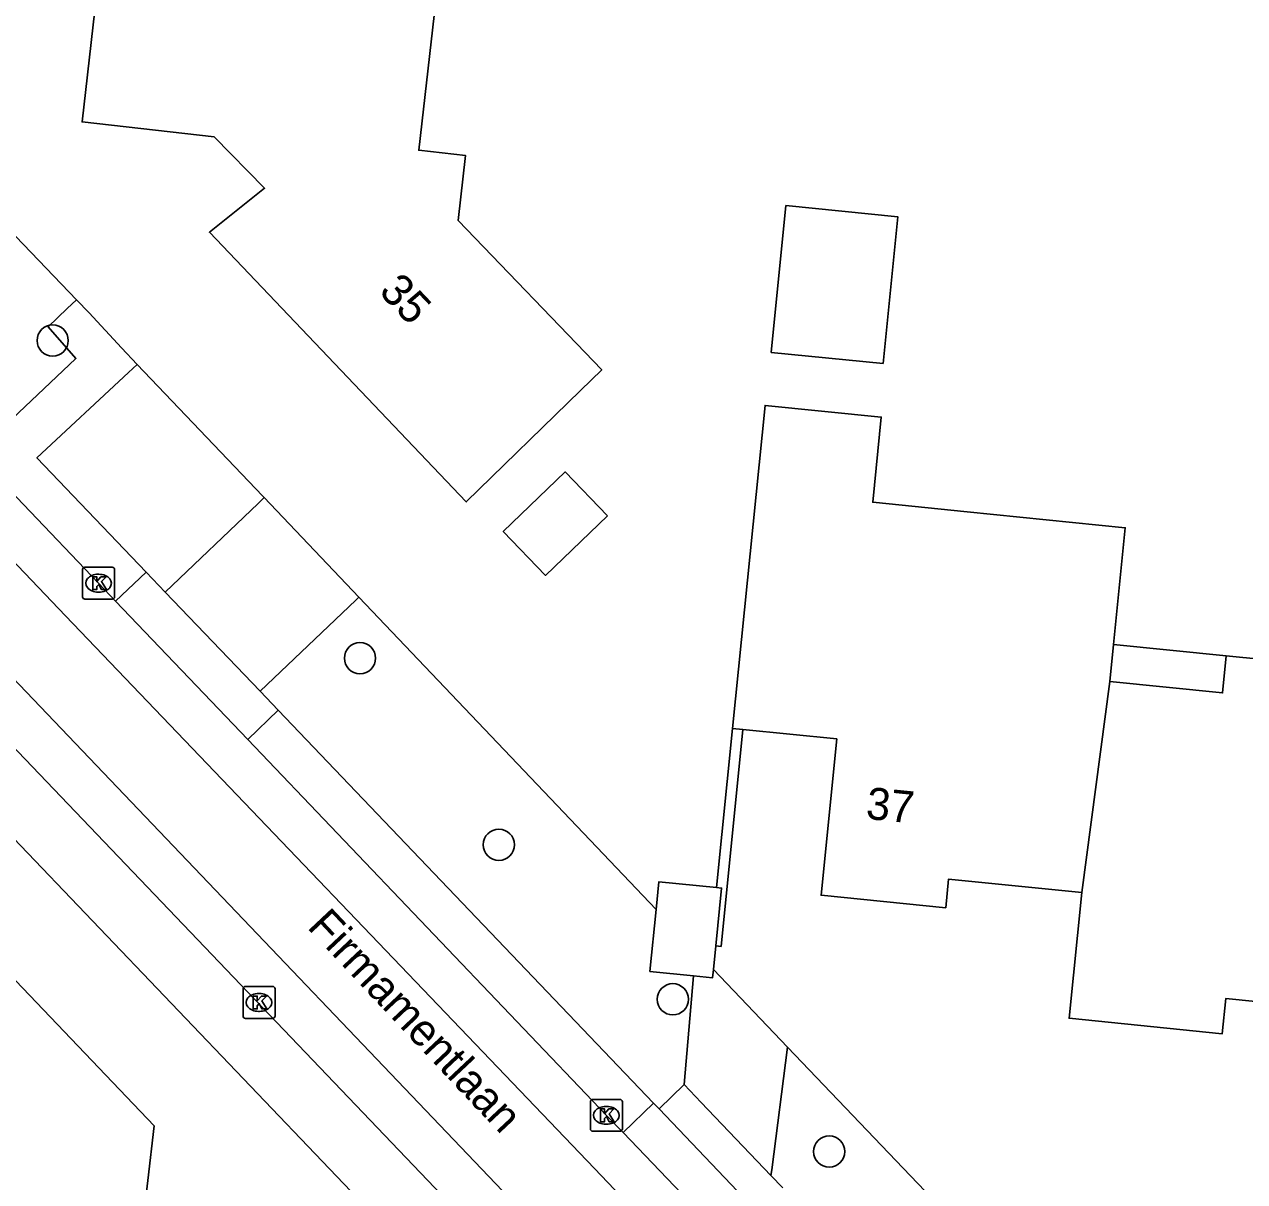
# Model space of a CAD drawing. Extents: x 162398 to 163643, y 386453 to 387397.
# Drawn here: x 162909.4 to 162947.59, y 386547.61 to 386583.81 of the extents above; entities that cross this region are included whole.
import ezdxf

# ---------------------------------------------------------------- set-up
doc = ezdxf.new("R2010")
doc.units = 0
for name, color, linetype in [('IMGEO_Boom', 7, 'Continuous'), ('IMGEO_Groenvoorziening', 7, 'Continuous'), ('IMGEO_Kolk', 7, 'Continuous'), ('IMGEO_Muur', 7, 'Continuous'), ('IMGEO_Openbare_ruimte_label', 7, 'Continuous'), ('IMGEO_Pand', 7, 'Continuous'), ('IMGEO_Pand_nummerreeks', 7, 'Continuous'), ('IMGEO_Pand_overbouw', 7, 'Continuous'), ('IMGEO_Rijbaan_lokaal_gesloten', 7, 'Continuous'), ('IMGEO_Rijbaan_lokaal_open', 7, 'Continuous'), ('IMGEO_Voetpad_open', 7, 'Continuous')]:
    doc.layers.add(name, color=color, linetype=linetype)

msp = doc.modelspace()

# ---------------------------------------------------------------- linework, layer by layer
at = {"layer": 'IMGEO_Boom'}
for centre in [(162910.287, 386573.918), (162919.905, 386563.982), (162924.253, 386558.146), (162929.696, 386553.311), (162934.592, 386548.547)]:
    msp.add_circle(centre, 0.489, dxfattribs=at)
at = {"layer": 'IMGEO_Groenvoorziening'}
for points in [[(162900.182, 386586.506), (162903.668, 386582.872), (162911.033, 386575.194)], [(162912.934, 386573.174), (162916.859, 386569.062), (162916.91, 386569.008)], [(162929.173, 386556.123), (162919.87, 386565.89)], [(162933.283, 386551.818), (162942.574, 386542.105), (162945.807, 386538.725), (162945.838, 386538.694)]]:
    msp.add_lwpolyline(points, dxfattribs=at)
at = {"layer": 'IMGEO_Kolk'}
for p, q in [((162911.298, 386566.828), (162912.15, 386566.828)), ((162911.223, 386565.902), (162911.223, 386566.754)), ((162911.711, 386566.608), (162911.736, 386566.608)), ((162912.224, 386566.754), (162912.224, 386565.902)), ((162912.15, 386565.828), (162911.298, 386565.828)), ((162911.734, 386566.048), (162911.709, 386566.048)), ((162916.245, 386552.786), (162916.245, 386553.638)), ((162916.32, 386553.712), (162917.172, 386553.712)), ((162916.733, 386553.492), (162916.758, 386553.492)), ((162917.246, 386553.638), (162917.246, 386552.786)), ((162917.172, 386552.712), (162916.32, 386552.712)), ((162916.756, 386552.932), (162916.731, 386552.932)), ((162927.115, 386549.255), (162927.115, 386550.107)), ((162927.19, 386550.181), (162928.042, 386550.181)), ((162928.116, 386550.107), (162928.116, 386549.255)), ((162927.603, 386549.961), (162927.628, 386549.961)), ((162927.626, 386549.401), (162927.601, 386549.401)), ((162928.042, 386549.181), (162927.19, 386549.181))]:
    msp.add_line(p, q, dxfattribs=at)
for points in [[(162911.298, 386566.828), (162912.15, 386566.828)], [(162911.223, 386565.902), (162911.223, 386566.754)], [(162911.544, 386566.528), (162911.667, 386566.528), (162911.667, 386566.377), (162911.797, 386566.528), (162911.961, 386566.528), (162911.815, 386566.377), (162911.968, 386566.128), (162911.816, 386566.128), (162911.731, 386566.292), (162911.667, 386566.225), (162911.667, 386566.128), (162911.544, 386566.128), (162911.544, 386566.528)], [(162912.224, 386566.754), (162912.224, 386565.902)], [(162912.15, 386565.828), (162911.298, 386565.828)], [(162916.245, 386552.786), (162916.245, 386553.638)], [(162916.32, 386553.712), (162917.172, 386553.712)], [(162917.246, 386553.638), (162917.246, 386552.786)], [(162916.566, 386553.412), (162916.689, 386553.412), (162916.689, 386553.261), (162916.819, 386553.412), (162916.983, 386553.412), (162916.837, 386553.261), (162916.99, 386553.012), (162916.838, 386553.012), (162916.753, 386553.176), (162916.689, 386553.109), (162916.689, 386553.012), (162916.566, 386553.012), (162916.566, 386553.412)], [(162917.172, 386552.712), (162916.32, 386552.712)], [(162927.115, 386549.255), (162927.115, 386550.107)], [(162927.19, 386550.181), (162928.042, 386550.181)], [(162928.116, 386550.107), (162928.116, 386549.255)], [(162927.436, 386549.881), (162927.559, 386549.881), (162927.559, 386549.73), (162927.689, 386549.881), (162927.853, 386549.881), (162927.707, 386549.73), (162927.86, 386549.481), (162927.708, 386549.481), (162927.623, 386549.645), (162927.559, 386549.578), (162927.559, 386549.481), (162927.436, 386549.481), (162927.436, 386549.881)], [(162928.042, 386549.181), (162927.19, 386549.181)]]:
    msp.add_lwpolyline(points, dxfattribs=at)
for centre, start, end in [((162911.3, 386566.752), 91.552, 178.448), ((162911.3, 386566.752), 91.552, 178.448), ((162912.148, 386566.752), 1.552, 88.448), ((162912.148, 386566.752), 1.552, 88.448), ((162911.3, 386565.904), 181.552, 268.448), ((162911.3, 386565.904), 181.552, 268.448), ((162912.148, 386565.904), 271.552, 358.448), ((162912.148, 386565.904), 271.552, 358.448), ((162916.322, 386553.636), 91.552, 178.448), ((162916.322, 386553.636), 91.552, 178.448), ((162917.17, 386553.636), 1.552, 88.448), ((162917.17, 386553.636), 1.552, 88.448), ((162916.322, 386552.788), 181.552, 268.448), ((162916.322, 386552.788), 181.552, 268.448), ((162917.17, 386552.788), 271.552, 358.448), ((162917.17, 386552.788), 271.552, 358.448), ((162927.192, 386550.105), 91.552, 178.448), ((162927.192, 386550.105), 91.552, 178.448), ((162928.04, 386550.105), 1.552, 88.448), ((162928.04, 386550.105), 1.552, 88.448), ((162927.192, 386549.257), 181.552, 268.448), ((162927.192, 386549.257), 181.552, 268.448), ((162928.04, 386549.257), 271.552, 358.448), ((162928.04, 386549.257), 271.552, 358.448)]:
    msp.add_arc(centre, 0.0765, start, end, dxfattribs=at)
for centre, major_axis, ratio, start_param, end_param in [((162911.71, 386566.328), (-0.387, 0.002), 0.722429, 4.712389, 7.853982), ((162911.735, 386566.328), (-0.39, 0.002), 0.717154, 1.570796, 4.712389), ((162916.732, 386553.212), (-0.387, 0.002), 0.722429, 4.712389, 7.853982), ((162916.757, 386553.212), (-0.39, 0.002), 0.717154, 1.570796, 4.712389), ((162927.602, 386549.681), (-0.387, 0.002), 0.722429, 4.712389, 7.853982), ((162927.627, 386549.681), (-0.39, 0.002), 0.717154, 1.570796, 4.712389)]:
    msp.add_ellipse(centre, major_axis=major_axis, ratio=ratio, start_param=start_param, end_param=end_param, dxfattribs=at)
at = {"layer": 'IMGEO_Muur'}
for points in [[(162931.887, 386561.751), (162931.204, 386554.964), (162931.042, 386554.98)], [(162931.068, 386556.804), (162931.568, 386561.783)]]:
    msp.add_lwpolyline(points, dxfattribs=at)
at = {"layer": 'IMGEO_Pand'}
for points in [[(162922.61, 386587.482), (162921.746, 386579.873), (162923.211, 386579.706), (162922.98, 386577.67), (162927.471, 386573.005), (162926.81, 386572.36), (162923.23, 386568.869), (162915.192, 386577.308), (162916.92, 386578.683), (162915.338, 386580.288), (162911.208, 386580.757), (162912.107, 386588.672)], [(162936.276, 386573.196), (162932.776, 386573.547), (162933.237, 386578.142), (162936.737, 386577.79), (162936.276, 386573.196)], [(162943.37, 386563.251), (162946.902, 386562.896), (162947.019, 386564.058), (162949.438, 386563.815), (162949.74, 386566.819), (162950.889, 386566.703), (162951.555, 386573.318), (162955.735, 386572.897)], [(162943.37, 386563.251), (162943.487, 386564.413), (162943.854, 386568.063), (162938.912, 386568.56), (162935.951, 386568.858), (162936.219, 386571.523), (162932.584, 386571.888), (162931.568, 386561.783)], [(162927.65, 386568.43), (162925.707, 386566.571), (162924.387, 386567.95), (162926.329, 386569.809), (162927.65, 386568.43)], [(162942.495, 386556.654), (162943.37, 386563.251)], [(162931.568, 386561.783), (162931.887, 386561.751)], [(162931.887, 386561.751), (162934.825, 386561.456), (162934.334, 386556.567), (162938.237, 386556.174), (162938.327, 386557.073), (162942.495, 386556.654)], [(162954.845, 386561.445), (162954.411, 386557.117), (162951.55, 386557.406), (162950.235, 386557.539), (162949.784, 386553.051), (162947, 386553.331), (162946.89, 386552.235), (162942.099, 386552.717), (162942.495, 386556.654)], [(162931.068, 386556.804), (162929.26, 386556.986), (162929.173, 386556.123)], [(162931.042, 386554.98), (162931.224, 386556.788), (162931.068, 386556.804)], [(162930.341, 386554.043), (162928.977, 386554.181), (162929.173, 386556.123)], [(162930.967, 386554.24), (162931.042, 386554.98)], [(162930.341, 386554.043), (162930.941, 386553.983), (162930.967, 386554.24)]]:
    msp.add_lwpolyline(points, dxfattribs=at)
at = {"layer": 'IMGEO_Pand_overbouw'}
msp.add_lwpolyline([(162947.019, 386564.058), (162943.487, 386564.413), (162943.37, 386563.251), (162946.902, 386562.896)], close=True, dxfattribs=at)
at = {"layer": 'IMGEO_Rijbaan_lokaal_gesloten'}
for points in [[(162912.252, 386565.764), (162911.724, 386566.328), (162899.972, 386578.636), (162899.807, 386578.798)], [(162898.769, 386577.801), (162910.688, 386565.306), (162927.247, 386548.019), (162937.051, 386537.73)], [(162916.392, 386561.443), (162912.252, 386565.764)], [(162928.144, 386549.14), (162927.616, 386549.681), (162916.392, 386561.443)], [(162932.279, 386544.813), (162928.144, 386549.14)]]:
    msp.add_lwpolyline(points, dxfattribs=at)
at = {"layer": 'IMGEO_Rijbaan_lokaal_open'}
for points in [[(162935.196, 386535.999), (162928.541, 386542.947), (162908.569, 386563.845), (162896.93, 386576.053)], [(162896.266, 386574.519), (162896.361, 386574.474), (162927.42, 386542.002), (162927.552, 386541.858)]]:
    msp.add_lwpolyline(points, dxfattribs=at)
at = {"layer": 'IMGEO_Voetpad_open'}
for points in [[(162911.033, 386575.194), (162910.745, 386574.918), (162910.146, 386574.344), (162911.015, 386573.361), (162908.821, 386571.279), (162899.983, 386580.542)], [(162912.873, 386544.224), (162913.466, 386549.351), (162888.98, 386574.996)], [(162912.934, 386573.174), (162912.441, 386573.691), (162911.429, 386574.781), (162911.033, 386575.194)], [(162913.215, 386566.677), (162909.794, 386570.248), (162912.661, 386572.92), (162912.934, 386573.174)], [(162923.891, 386542.84), (162906.575, 386560.94), (162896.624, 386571.352)], [(162913.812, 386566.05), (162916.718, 386568.825), (162916.91, 386569.008)], [(162916.91, 386569.008), (162919.87, 386565.89)], [(162912.252, 386565.764), (162913.215, 386566.677)], [(162913.215, 386566.677), (162913.812, 386566.05)], [(162913.812, 386566.05), (162916.778, 386562.954)], [(162919.87, 386565.89), (162919.773, 386565.798), (162916.778, 386562.954)], [(162916.778, 386562.954), (162917.348, 386562.357)], [(162916.392, 386561.443), (162917.348, 386562.357)], [(162917.348, 386562.357), (162929.095, 386550.057)], [(162933.283, 386551.818), (162930.967, 386554.24)], [(162930.054, 386550.644), (162930.341, 386554.043)], [(162932.768, 386547.803), (162932.791, 386547.981), (162933.283, 386551.818)], [(162929.272, 386549.883), (162930.054, 386550.644)], [(162930.054, 386550.644), (162930.587, 386550.086), (162932.768, 386547.803)], [(162929.095, 386550.057), (162928.144, 386549.14)], [(162929.095, 386550.057), (162929.272, 386549.883)], [(162929.272, 386549.883), (162932.337, 386546.664)], [(162933.139, 386547.414), (162932.768, 386547.803)]]:
    msp.add_lwpolyline(points, dxfattribs=at)

# ---------------------------------------------------------------- texts
at = {"layer": 'IMGEO_Openbare_ruimte_label'}
msp.add_text('Firmamentlaan', height=1, rotation=313.2177, dxfattribs=at).set_placement((162918.225, 386555.557))
at = {"layer": 'IMGEO_Pand_nummerreeks'}
for s, rotation, p in [('35', 313.6059, (162920.466, 386575.426)), ('37', 354.2475, (162935.716, 386558.96))]:
    msp.add_text(s, height=1, rotation=rotation, dxfattribs=at).set_placement(p)

doc.saveas('drawing.dxf')
